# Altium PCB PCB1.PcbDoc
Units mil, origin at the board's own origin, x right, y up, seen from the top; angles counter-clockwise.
Board outline 6000 x 4000 mil, 2 copper layers (Top Layer, Bottom Layer); 9 components, 8 nets, 33 pads, 3 vias.
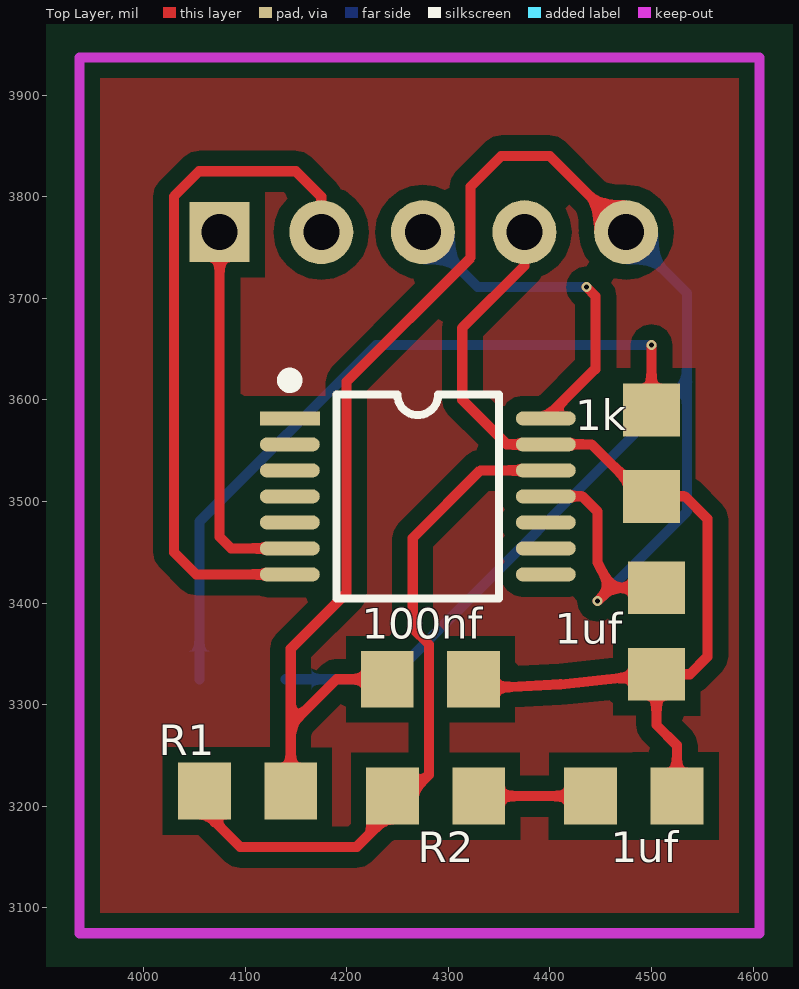
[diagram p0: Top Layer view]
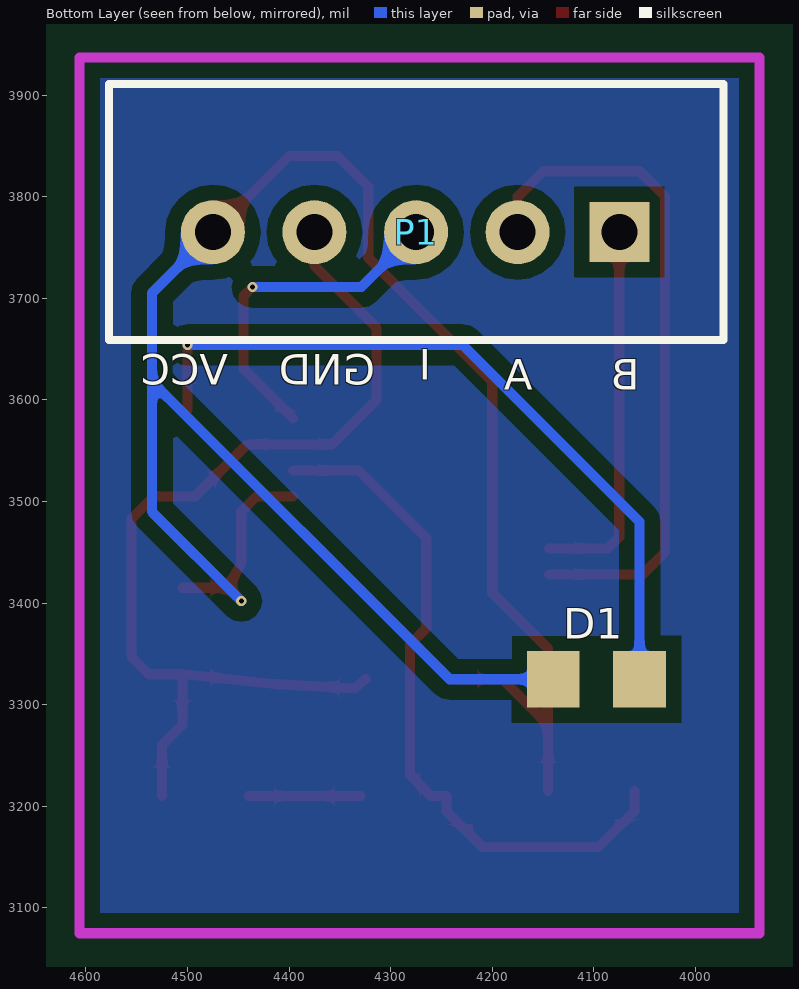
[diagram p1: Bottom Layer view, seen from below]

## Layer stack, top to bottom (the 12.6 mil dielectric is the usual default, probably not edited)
Top Solder: solder mask 0.4, Solder Resist, Dk 3.5
Top Layer: signal copper 1.4
Dielectric1: dielectric 12.6, FR-4, Dk 4.8
Bottom Layer: signal copper 1.4
Bottom Solder: solder mask 0.4, Solder Resist, Dk 3.5

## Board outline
2580,2130 2580,6130 8580,6130 8580,2130

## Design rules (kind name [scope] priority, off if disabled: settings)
AssemblyTestPointUsage AssemblyTestPointUsage_1 [All] p2:
AssemblyTestpoint AssemblyTestpoint_1 [All] p2: testpointundercomponent=TRUE minsize=40 maxsize=100 preferedsize=60 minholesize=0 maxholesize=40 preferedholesize=32 testpointgrid=1 usegrid=TRUE gridtolerance=0.01 allowsidetop=TRUE allowsidebottom=TRUE
Clearance Clearance_1 [InPolygon] p1: gap=15
Clearance [All] p2: gap=10
ComponentClearance ComponentClearance_1 [All] p2: gap=10 collisioncheckmode=3 verticalgap=10 showdistances=FALSE
DiffPairsRouting DiffPairsRouting_1 [All] p2: maxlimit=10 minlimit=10 mostfreqgap=10 toplayer_minwidth=15 toplayer_maxwidth=15 toplayer_prefwidth=15 bottomlayer_minwidth=15 bottomlayer_maxwidth=15 bottomlayer_prefwidth=15 maxuncoupledlength=500
FabricationTestPointUsage TestPointUsage [All] p2: valid=0 allowmultiple=FALSE
FabricationTestpoint Testpoint [All] p2: side=3 testpointundercomponent=TRUE minsize=40 maxsize=100 preferedsize=60 minholesize=0 maxholesize=40 preferedholesize=32 testpointgrid=1 allowsidetop=TRUE allowsidebottom=TRUE usegrid=TRUE gridtolerance=0.01
FanoutControl Fanout_LCC [IsLCC] p1: bgadir=Out bgaviamode=Centered fanoutstyle=Auto fanoutdirection=Alternating viagrid=1 // Fanout_LCC (Default Rule)
FanoutControl Fanout_BGA [IsBGA] p2: bgadir=Out bgaviamode=Centered fanoutstyle=Auto fanoutdirection=Alternating viagrid=1 // Fanout_BGA (Default Rule)
FanoutControl Fanout_Default [All] p4: bgadir=Out bgaviamode=Centered fanoutstyle=Auto fanoutdirection=Alternating viagrid=1 // Fanout_Default (Default Rule)
FanoutControl Fanout_Small [(CompPinCount < 5)] p5: bgadir=Out bgaviamode=Centered fanoutstyle=Auto fanoutdirection=OutThenIn viagrid=1 // Fanout_Small (Default Rule)
FanoutControl Fanout_BGA_1 [IsBGA] p6: bgadir=Out bgaviamode=Centered fanoutstyle=Auto fanoutdirection=Alternating viagrid=1 // Fanout_BGA (Default Rule)
FanoutControl Fanout_LCC_1 [IsLCC] p7: bgadir=Out bgaviamode=Centered fanoutstyle=Auto fanoutdirection=Alternating viagrid=1 // Fanout_LCC (Default Rule)
FanoutControl Fanout_SOIC_1 [IsSOIC] p8: bgadir=Out bgaviamode=Centered fanoutstyle=Auto fanoutdirection=Alternating viagrid=1 // Fanout_SOIC (Default Rule)
FanoutControl Fanout_Small_1 [(CompPinCount < 5)] p9: bgadir=Out bgaviamode=Centered fanoutstyle=Auto fanoutdirection=OutThenIn viagrid=1 // Fanout_Small (Default Rule)
FanoutControl Fanout_Default_1 [All] p10: bgadir=Out bgaviamode=Centered fanoutstyle=Auto fanoutdirection=Alternating viagrid=1 // Fanout_Default (Default Rule)
Height Height_1 [All] p2: minheight=0 maxheight=1000 prefheight=500
HoleSize HoleSize_1 [All] p2: absolutevalues=TRUE maxlimit=100 minlimit=1 maxpercent=80.000 minpercent=20.000
HoleToHoleClearance HoleToHoleClearance_1 [All] p2: gap=10 allowstackedmicrovias=TRUE
LayerPairs LayerPairs_1 [All] p2: enforce=TRUE
MinimumSolderMaskSliver MinimumSolderMaskSliver_1 [All] p2: minsoldermaskwidth=10
NetAntennae NetAntennae_1 [All] p2: netantennaetolerance=0
PasteMaskExpansion PasteMaskExpansion_1 [All] p2: expansion=0
PlaneClearance PlaneClearance_1 [All] p2: clearance=20
PolygonConnect [All] p1: connectstyle=Relief reliefconductorwidth=10 reliefentries=4 polygonreliefangle="90 Angle" airgapwidth=10
PolygonConnect PolygonConnect_1 [All] p2: connectstyle=Relief reliefconductorwidth=10 reliefentries=4 polygonreliefangle="90 Angle" airgapwidth=10
RoutingPriority RoutingPriority_1 [All] p2: routingpriority=0
RoutingTopology RoutingTopology_1 [All] p2: topology=Shortest
RoutingVias [All] p1: holewidth=25 width=40 viastyle="Through Hole" minholewidth=28 minwidth=50 maxholewidth=28 maxwidth=50
ShortCircuit ShortCircuit_1 [All] p2: allowed=FALSE
SilkToBoardRegionClearance SilkToBoardRegionClearance_1 [All] p2:
SilkToSilkClearance SilkToSilkClearance_1 [All] p2: silktosilkclearance=10
SilkToSolderMaskClearance SilkscreenOverComponentPads [IsPad] p2: minsilkscreentomaskgap=10 clearancetoexposedcopper=TRUE
SolderMaskExpansion [All] p1: expansion=4
SolderMaskExpansion SolderMaskExpansion_1 [All] p2: expansion=4
UnRoutedNet UnRoutedNet_1 [All] p2:
UnpouredPolygon UnpouredPolygon_1 [All] p2:
Width [All] p1: maxlimit=10 minlimit=10 preferedwidth=10
26 further rules are at their usual default settings.

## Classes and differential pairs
component class оƬ: 1k 1uf 100nf D1 R1 R2

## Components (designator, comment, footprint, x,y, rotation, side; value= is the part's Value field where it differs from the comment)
1k "Res1" 0805 4560,3295 r90 top (schematic designator R3)
1uf "Cap" 0805 4565,3120 r90 top (schematic designator C3)
1uf "Cap" 0805 4735,3270 r180 top (schematic designator C2)
100nf "Cap" 0805 4030,3265 r0 top (schematic designator C1)
D1 "LED0" 0805 4350,3265 r180 bottom
P1 "Header 5H" 5pin_XH2.54 4015,3575 r90 bottom
R1 "Res2" 0805 3850,3155 r0 top
R2 "Res2" 0805 4035,3150 r0 top
U1 "MHDR2X7" SSOP14 4270,3505 r0 top

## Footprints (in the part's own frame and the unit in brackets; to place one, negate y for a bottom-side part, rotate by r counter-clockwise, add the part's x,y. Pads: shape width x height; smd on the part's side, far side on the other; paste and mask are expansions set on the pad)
5pin_XH2.54 [mm]
  rect 1.5x1.5 hole 0.9: 1(4.826,1.524)
  round 1.6 hole 0.9: 2(4.826,4.064) 3(4.826,6.604) 4(4.826,9.144) 5(4.826,11.684)
  silkscreen extent 2.13,-1.08 8.53,14.28
0805 [mil]
  rect 52x56 smd: 1(210,60) 2(295,60)
SSOP14 [mm] "5*6.4*1.2mm（蒜米工坊）"
  rect 1.5x0.35 smd: 1(-3.2,1.95)
  oval 1.5x0.35 smd: 2(-3.2,1.3) 3(-3.2,0.65) 4(-3.2,0) 5(-3.2,-0.65) 6(-3.2,-1.3) 7(-3.2,-1.95) 8(3.2,-1.95) 9(3.2,-1.3) 10(3.2,-0.65) 11(3.2,0) 12(3.2,0.65) 13(3.2,1.3) 14(3.2,1.95)
  silkscreen extent -3.33,-2.55 2.03,3.03, body extent -3.2,-2.5 3.2,2.5, height 1.25

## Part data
1k R1 R2: "Resistor"
1uf 1uf 100nf: "Capacitor"
D1: "Typical INFRARED GaAs LED"
P1: "Header, 5-Pin, Right Angle"
U1: "Header, 7-Pin, Dual row"

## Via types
v1: diameter 10, hole 5, Top Layer to Bottom Layer, 3 vias

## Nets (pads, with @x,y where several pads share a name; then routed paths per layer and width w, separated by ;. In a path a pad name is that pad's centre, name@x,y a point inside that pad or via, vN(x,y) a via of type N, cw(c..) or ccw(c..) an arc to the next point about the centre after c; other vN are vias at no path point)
3.3V/5V: 1uf.2@4505,3415 100nf.1 D1.1 P1.5 R1.2 U1.11 | length 2117.9
  Top Layer w10: R1.2 4145,3280 ; 100nf.1 4190,3325 4145,3280 ; U1.11 4432,3505 4447,3490 4447,3440 4460,3415 ; v1(4447,3402) 4460,3415 ; P1.5 4400,3840 4352,3840 4322,3810 4322,3740 4200,3618 4200,3410 4145,3355 4145,3280 ; 1uf.2@4505,3415 4460,3415
  Bottom Layer w10: D1.1 4242,3325 4535,3618 ; v1(4447,3402) 4535,3490 4535,3618 ; P1.5 4535,3705 4535,3618
A: P1.2 U1.7 | length 673.9
  Top Layer w10: U1.7 4051.77,3428.23 4030,3450 4030,3800.27 4054.73,3825 4150,3825 4175,3800 P1.2
B: P1.1 U1.6 | length 373.6
  Top Layer w10: P1.1 4075,3465 4086.18,3453.82 U1.6
GND: 1k.1 1uf.1 100nf.2 P1.4 U1.13 | length 985.4
  Top Layer w10: 100nf.2 4334.94,3316.05 4410.52,3320.03 1uf.1@4505,3330 ; P1.4 4375,3732.01 4313.82,3670.83 4313.82,3600 4357.64,3556.18 U1.13 4441,3556.18 4492.18,3505 1k.1 4533,3505 4555,3483 4555,3347 4538,3330 1uf.1@4505,3330 ; 1uf.1@4525,3210 4525,3260 4505,3280 1uf.1@4505,3330
I/PWM: P1.3 U1.14 | length 337.1
  Top Layer w10: U1.14 4444.21,3630 4445,3630 4445,3702 v1(4436,3711)
  Bottom Layer w10: P1.3 4329,3711 v1(4436,3711)
NetC2_2: 1uf.2@4440,3210 R2.2 | length 110
  Top Layer w10: R2.2 1uf.2@4440,3210
NetD1_2: 1k.2 D1.2 | length 736.1
  Top Layer w10: 1k.2 v1(4500,3654)
  Bottom Layer w10: D1.2 4055,3480 4229,3654 v1(4500,3654)
VDD3V: R1.1 R2.1 U1.12 | length 691.9
  Top Layer w10: R1.1 4060,3195 4095,3160 4210,3160 4245,3195 R2.1 4260,3210 4281,3231 4281,3359.21 4265,3375.21 4265,3464 4331.59,3530.59 U1.12
pads on no net: U1.1 U1.2 U1.3 U1.4 U1.5 U1.8 U1.9 U1.10

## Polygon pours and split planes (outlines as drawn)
no net on Top Layer "Top Layer-No Net" (solid, pour order 14): 3937.01,3937.01 4606.3,3937.01 4606.3,3086.3 4600,3080 4595,3075 3937.01,3075 3937.01,3937.01
no net on Bottom Layer "Top Layer-No Net" (solid, pour order 16): 3937.01,3937.01 4600,3937.01 4600,3081.3 4606.3,3075 3937.01,3075 3937.01,3937.01

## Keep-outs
Keep-Out Layer:
  lines w10: 3937.01,3075 3937.01,3937.01 4606.3,3937.01 4606.3,3075 3937.01,3075

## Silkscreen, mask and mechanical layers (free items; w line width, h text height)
Bottom Overlay:
  text "I" at 4260,3620 h30
  text "GND" at 4315,3615 h30
  text "VCC" at 4460,3615 h30
  text "B" at 4055,3610 h30
  text "A" at 4160,3610 h30
Mechanical 16:
  drawing of 1874 lines, arcs and shapes, not listed
  text "1" at 1427,7465 h70
  text "2" at 4287,7465 h70
  text "3" at 7167,7465 h70
  text "4" at 10037,7465 h70
  text "A" at 75,6559 h70
  text "A" at 11375,6559 h70
  text "B" at 75,4667 h70
  text "B" at 11375,4667 h70
  text "C" at 75,2757 h70
  text "C" at 11375,2757 h70
  text "ENGINEER:" at 6850,1300 h45
  text "TITLE:" at 8350,1300 h45
  text "PCB DESIGNER:" at 6850,1005 h45
  text "D" at 75,867 h70
  text "D" at 11375,867 h70
  text "DATE:" at 6850,700 h45
  text "PART NO.:" at 8350,700 h45
  text "REV:" at 10450,700 h45
  text "Altium Limited" at 5550,600 h70
  text ".PRINT_DATE" at 6900,580 h70
  text "12a Rodborough Rd" at 5550,500 h70
  text "Frenchs Forest" at 5550,400 h70
  text "FILE NAME:" at 6850,400 h45
  text "DWG NO:" at 8350,400 h45
  text "SCALE:" at 10450,400 h45
  text "NSW 2086" at 5550,300 h70
  text ".PCB_FILE_NAME_NO_PATH" at 6900,280 h70
  text "1" at 1427,65 h70
  text "2" at 4287,65 h70
  text "3" at 7167,65 h70
  text "4" at 10037,65 h70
